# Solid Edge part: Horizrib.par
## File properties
Author: harmonj5
Template: ansi part.par
Last saved by: harmonj5
Revision: 6
Application: Solid Edge
Accuracy: 0.990
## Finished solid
Body 1: solid body, 59 faces, 165 edges, 110 vertices, 2 separate solids.
  Faces by surface: plane 38, cylinder 11, swept 10
  Edges by curve: line 123, circle 22, spline 20
Bounding box of the edges (mm; curved faces can reach further): 185.489 x 3.175 x 17.663, from (-133.9507, -3.175, 34.9527) to (51.5387, 0, 52.6154).
Cylindrical faces by radius (mm): R3.175 x8, R101.8963 x1, R162.1833 x1, R189.7875 x1
Planar faces by outward normal: +x 10, +y 2, +z 6, -x 6, -y 2, -z 3, oblique 9
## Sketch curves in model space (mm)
line (-133.9507, 0, 42.0053) -> (-133.157, 0, 42.0053)
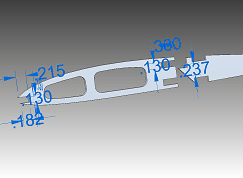
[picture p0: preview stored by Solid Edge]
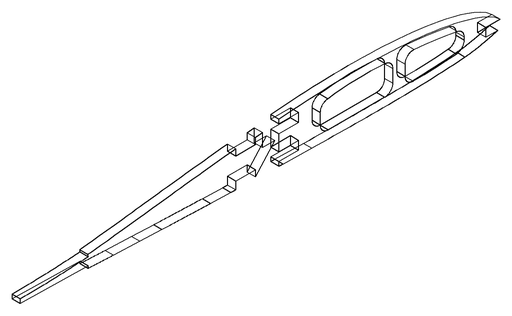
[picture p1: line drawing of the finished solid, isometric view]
